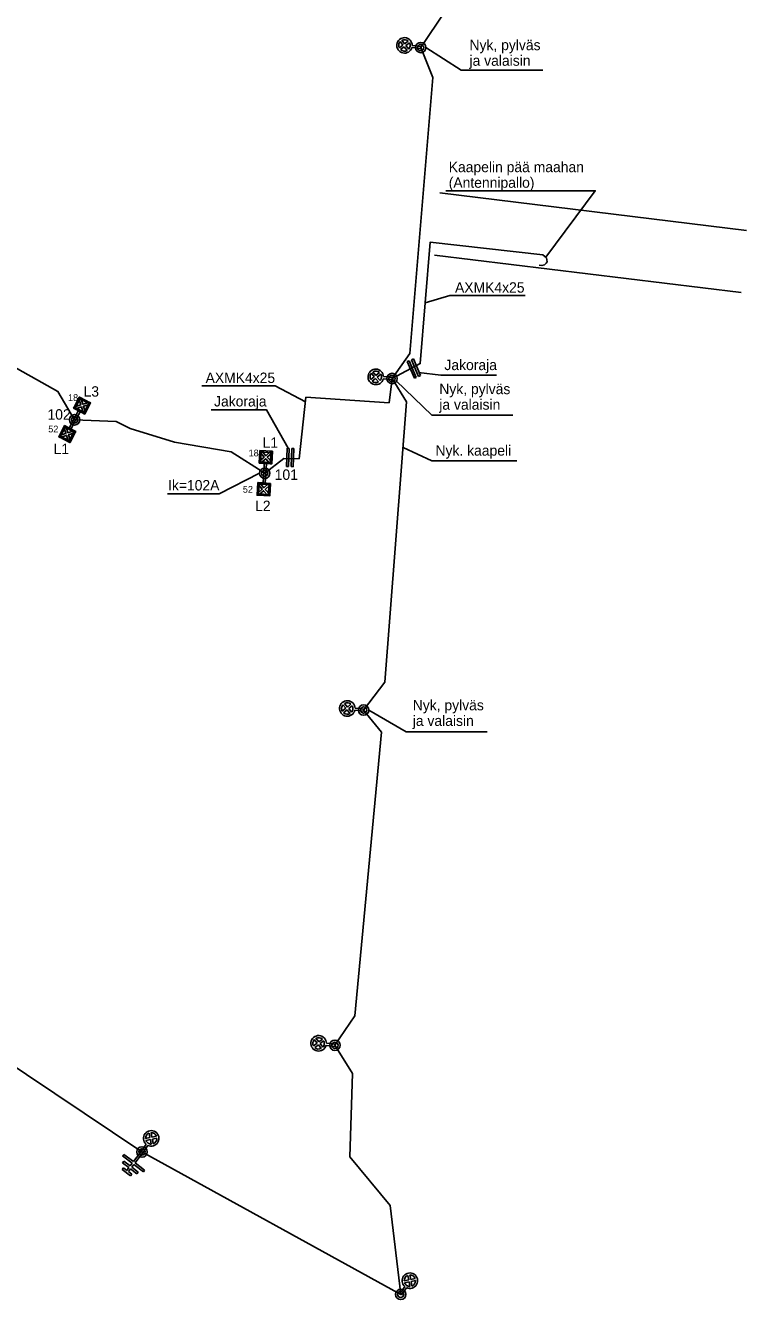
# Model space of a CAD drawing. Extents: x 25497852 to 25498297, y 6686544 to 6687252.
# Drawn here: x 25498193.2 to 25498297.2, y 6686878.8 to 6687062.7 of the extents above; entities that cross this region are included whole.
import ezdxf

# ---------------------------------------------------------------- set-up
doc = ezdxf.new("R2010")
doc.units = 0
for name, color, linetype in [('KayttoOikeusYksikko_piste_tunnus', 7, 'Continuous'), ('KiinteistoNimi', 7, 'Continuous'), ('Rajamerkki_maarekisteripyykki', 7, 'Continuous'), ('Rajamerkki_tonttipyykki', 7, 'Continuous'), ('Rasitealue', 7, 'Continuous'), ('Rasiteviiva', 7, 'Continuous'), ('Taso 1', 7, 'Continuous')]:
    doc.layers.add(name, color=color, linetype=linetype)

msp = doc.modelspace()

# ---------------------------------------------------------------- linework, layer by layer
at = {"layer": 'KayttoOikeusYksikko_piste_tunnus'}
for p, q in [((25498247.66, 6687059.83), (25498247.14, 6687059.43)), ((25498247.26, 6687060.35), (25498247.66, 6687059.83)), ((25498247.32, 6687059.19), (25498247.84, 6687059.59)), ((25498247.9, 6687060.01), (25498247.5, 6687060.54)), ((25498247.84, 6687059.59), (25498248.24, 6687059.06)), ((25498248.43, 6687060.41), (25498247.9, 6687060.01)), ((25498248.08, 6687059.77), (25498248.61, 6687060.17)), ((25498248.48, 6687059.24), (25498248.08, 6687059.77)), ((25498250.2, 6687059.33), (25498248.96, 6687059.5)), ((25498249, 6687059.8), (25498250.24, 6687059.63)), ((25498250.24, 6687059.63), (25498250.2, 6687059.33)), ((25498243.52, 6687011.97), (25498243, 6687011.56)), ((25498243.1, 6687012.49), (25498243.52, 6687011.97)), ((25498243.19, 6687011.32), (25498243.71, 6687011.74)), ((25498243.75, 6687012.16), (25498243.33, 6687012.68)), ((25498243.71, 6687011.74), (25498244.12, 6687011.23)), ((25498244.26, 6687012.58), (25498243.75, 6687012.16)), ((25498243.94, 6687011.93), (25498244.45, 6687012.35)), ((25498244.36, 6687011.42), (25498243.94, 6687011.93)), ((25498246.07, 6687011.57), (25498244.82, 6687011.69)), ((25498244.85, 6687011.99), (25498246.1, 6687011.86)), ((25498246.1, 6687011.86), (25498246.07, 6687011.57)), ((25498239.41, 6686964.11), (25498238.9, 6686963.7)), ((25498238.99, 6686964.63), (25498239.41, 6686964.11)), ((25498239.08, 6686963.46), (25498239.6, 6686963.88)), ((25498239.64, 6686964.3), (25498239.22, 6686964.82)), ((25498239.6, 6686963.88), (25498240.01, 6686963.37)), ((25498240.15, 6686964.72), (25498239.64, 6686964.3)), ((25498239.83, 6686964.07), (25498240.34, 6686964.49)), ((25498240.25, 6686963.56), (25498239.83, 6686964.07)), ((25498241.96, 6686963.7), (25498240.71, 6686963.83)), ((25498240.74, 6686964.13), (25498241.99, 6686964)), ((25498241.99, 6686964), (25498241.96, 6686963.7)), ((25498235.27, 6686915.77), (25498234.75, 6686915.37)), ((25498234.86, 6686916.29), (25498235.27, 6686915.77)), ((25498235.51, 6686915.96), (25498235.1, 6686916.48)), ((25498236.03, 6686916.37), (25498235.51, 6686915.96)), ((25498235.69, 6686915.72), (25498236.21, 6686916.13)), ((25498236.1, 6686915.2), (25498235.69, 6686915.72)), ((25498236.61, 6686915.76), (25498237.85, 6686915.61)), ((25498237.85, 6686915.61), (25498237.82, 6686915.31)), ((25498234.94, 6686915.13), (25498235.46, 6686915.54)), ((25498235.46, 6686915.54), (25498235.86, 6686915.02)), ((25498237.82, 6686915.31), (25498236.57, 6686915.46)), ((25498211.01, 6686902.8), (25498211.14, 6686902.15)), ((25498211.43, 6686902.21), (25498211.31, 6686902.86)), ((25498209.87, 6686900.15), (25498210.57, 6686901.19)), ((25498210.82, 6686901.02), (25498210.12, 6686899.98)), ((25498211.14, 6686902.15), (25498210.49, 6686902.02)), ((25498210.55, 6686901.73), (25498211.2, 6686901.86)), ((25498211.2, 6686901.86), (25498211.32, 6686901.21)), ((25498212.08, 6686902.33), (25498211.43, 6686902.21)), ((25498211.49, 6686901.91), (25498212.14, 6686902.04)), ((25498211.62, 6686901.26), (25498211.49, 6686901.91)), ((25498210.12, 6686899.98), (25498209.87, 6686900.15)), ((25498247.21, 6686879.61), (25498247.91, 6686880.65)), ((25498248.48, 6686881.61), (25498247.83, 6686881.48)), ((25498247.88, 6686881.19), (25498248.53, 6686881.31)), ((25498248.35, 6686882.26), (25498248.48, 6686881.61)), ((25498248.53, 6686881.31), (25498248.66, 6686880.67)), ((25498248.77, 6686881.67), (25498248.64, 6686882.32)), ((25498249.42, 6686881.79), (25498248.77, 6686881.67)), ((25498248.83, 6686881.37), (25498249.48, 6686881.5)), ((25498248.96, 6686880.72), (25498248.83, 6686881.37)), ((25498247.45, 6686879.44), (25498247.21, 6686879.61)), ((25498248.15, 6686880.48), (25498247.45, 6686879.44))]:
    msp.add_line(p, q, dxfattribs=at)
for points in [[(25498200.11, 6687007.42), (25498200.21, 6687007.6), (25498201.77, 6687006.78), (25498201.68, 6687006.61)], [(25498200.93, 6687008.99), (25498200.14, 6687007.48), (25498200.32, 6687007.38), (25498201.11, 6687008.89)], [(25498201.52, 6687006.76), (25498201.25, 6687007.62), (25498200.38, 6687007.35), (25498200.2, 6687007.45), (25498200.29, 6687007.64), (25498201.16, 6687007.91), (25498200.88, 6687008.77), (25498200.98, 6687008.96), (25498201.17, 6687008.86), (25498201.44, 6687008), (25498202.3, 6687008.27), (25498202.49, 6687008.17), (25498202.39, 6687007.98), (25498201.53, 6687007.71), (25498201.8, 6687006.85), (25498201.71, 6687006.66)], [(25498202.43, 6687008.05), (25498202.52, 6687008.22), (25498200.96, 6687009.04), (25498200.86, 6687008.86)], [(25498201.55, 6687006.67), (25498202.4, 6687008.29), (25498202.57, 6687008.2), (25498201.73, 6687006.58)], [(25498200.4, 6687005.68), (25498199.75, 6687004.44), (25498199.49, 6687004.57), (25498200.14, 6687005.82)], [(25498200.14, 6687005.82), (25498200.79, 6687007.07), (25498201.06, 6687006.93), (25498200.4, 6687005.68)], [(25498198.99, 6687004.84), (25498198.15, 6687003.22), (25498197.97, 6687003.31), (25498198.81, 6687004.93)], [(25498199.03, 6687004.75), (25498199.3, 6687003.89), (25498200.16, 6687004.16), (25498200.35, 6687004.06), (25498200.25, 6687003.87), (25498199.39, 6687003.6), (25498199.66, 6687002.74), (25498199.56, 6687002.55), (25498199.37, 6687002.65), (25498199.1, 6687003.51), (25498198.24, 6687003.24), (25498198.05, 6687003.34), (25498198.15, 6687003.53), (25498199.01, 6687003.8), (25498198.74, 6687004.66), (25498198.84, 6687004.85)], [(25498200.43, 6687004.08), (25498200.34, 6687003.91), (25498198.77, 6687004.72), (25498198.87, 6687004.9)], [(25498199.62, 6687002.52), (25498200.4, 6687004.03), (25498200.22, 6687004.12), (25498199.44, 6687002.61)], [(25498198.12, 6687003.46), (25498198.02, 6687003.28), (25498199.59, 6687002.47), (25498199.68, 6687002.64)], [(25498226.99, 6687001.26), (25498226.89, 6686999.56), (25498227.09, 6686999.55), (25498227.19, 6687001.25)], [(25498228.44, 6686999.47), (25498227.84, 6687000.14), (25498227.16, 6686999.55), (25498226.95, 6686999.56), (25498226.96, 6686999.77), (25498227.64, 6687000.37), (25498227.04, 6687001.04), (25498227.05, 6687001.26), (25498227.27, 6687001.24), (25498227.86, 6687000.57), (25498228.54, 6687001.16), (25498228.75, 6687001.15), (25498228.74, 6687000.94), (25498228.06, 6687000.34), (25498228.66, 6686999.67), (25498228.65, 6686999.45)], [(25498228.74, 6687001.01), (25498228.76, 6687001.21), (25498227, 6687001.32), (25498226.98, 6687001.12)], [(25498228.51, 6686999.4), (25498228.62, 6687001.22), (25498228.82, 6687001.21), (25498228.71, 6686999.39)], [(25498226.88, 6686999.5), (25498226.9, 6686999.7), (25498228.66, 6686999.59), (25498228.65, 6686999.39)], [(25498227.56, 6686998.05), (25498227.64, 6686999.45), (25498227.94, 6686999.44), (25498227.86, 6686998.03)], [(25498226.91, 6686996.68), (25498226.8, 6686994.86), (25498226.6, 6686994.87), (25498226.71, 6686996.69)], [(25498226.98, 6686996.61), (25498227.58, 6686995.94), (25498228.25, 6686996.54), (25498228.47, 6686996.52), (25498228.45, 6686996.31), (25498227.78, 6686995.71), (25498228.37, 6686995.04), (25498228.36, 6686994.83), (25498228.15, 6686994.84), (25498227.55, 6686995.51), (25498226.87, 6686994.92), (25498226.66, 6686994.93), (25498226.67, 6686995.14), (25498227.35, 6686995.74), (25498226.75, 6686996.42), (25498226.77, 6686996.63)], [(25498228.53, 6686996.58), (25498228.52, 6686996.38), (25498226.76, 6686996.49), (25498226.77, 6686996.69)], [(25498227.86, 6686998.03), (25498227.77, 6686996.63), (25498227.47, 6686996.65), (25498227.56, 6686998.05)], [(25498228.42, 6686994.82), (25498228.53, 6686996.52), (25498228.33, 6686996.53), (25498228.22, 6686994.83)], [(25498226.67, 6686995.07), (25498226.66, 6686994.87), (25498228.42, 6686994.76), (25498228.43, 6686994.96)]]:
    msp.add_lwpolyline(points, close=True, dxfattribs=at)
for centre, radius, start, end in [((25498247.87, 6687059.8), 1.12, 359.9115, 172.2492), ((25498247.87, 6687059.8), 1.12, 172.2492, 344.587), ((25498247.87, 6687059.8), 0.825, 137.7249, 172.2492), ((25498247.87, 6687059.8), 0.825, 172.2492, 206.7736), ((25498247.87, 6687059.8), 0.825, 227.7249, 296.7736), ((25498247.87, 6687059.8), 0.825, 47.7249, 116.7736), ((25498247.87, 6687059.8), 0.825, 317.7249, 352.2492), ((25498247.87, 6687059.8), 0.825, 352.2492, 26.7736), ((25498243.73, 6687011.95), 1.12, 1.8898, 174.2275), ((25498243.73, 6687011.95), 1.12, 174.2275, 346.5652), ((25498243.73, 6687011.95), 0.825, 174.2275, 208.7518), ((25498243.73, 6687011.95), 0.825, 139.7032, 174.2275), ((25498243.73, 6687011.95), 0.825, 229.7032, 298.7518), ((25498243.73, 6687011.95), 0.825, 49.7032, 118.7518), ((25498243.73, 6687011.95), 0.825, 319.7032, 354.2275), ((25498243.73, 6687011.95), 0.825, 354.2275, 28.7518), ((25498239.62, 6686964.09), 1.12, 174.1431, 346.4809), ((25498239.62, 6686964.09), 1.12, 1.8054, 174.1431), ((25498239.62, 6686964.09), 0.825, 174.1431, 208.6674), ((25498239.62, 6686964.09), 0.825, 139.6188, 174.1431), ((25498239.62, 6686964.09), 0.825, 229.6188, 298.6674), ((25498239.62, 6686964.09), 0.825, 49.6188, 118.6674), ((25498239.62, 6686964.09), 0.825, 319.6188, 354.1431), ((25498239.62, 6686964.09), 0.825, 354.1431, 28.6674), ((25498235.48, 6686915.75), 1.12, 173.0866, 345.4243), ((25498235.48, 6686915.75), 1.12, 0.7488, 173.0866), ((25498235.48, 6686915.75), 0.825, 138.5623, 173.0866), ((25498235.48, 6686915.75), 0.825, 173.0866, 207.6109), ((25498235.48, 6686915.75), 0.825, 48.5623, 117.6109), ((25498235.48, 6686915.75), 0.825, 318.5623, 353.0866), ((25498235.48, 6686915.75), 0.825, 353.0866, 27.6109), ((25498235.48, 6686915.75), 0.825, 228.5623, 297.6109), ((25498211.32, 6686902.03), 1.12, 56.0415, 228.3793), ((25498211.32, 6686902.03), 0.825, 111.5172, 180.5658), ((25498211.32, 6686902.03), 1.12, 243.7038, 56.0415), ((25498211.32, 6686902.03), 0.825, 56.0415, 90.5658), ((25498211.32, 6686902.03), 0.825, 21.5172, 56.0415), ((25498211.32, 6686902.03), 0.825, 201.5172, 236.0415), ((25498211.32, 6686902.03), 0.825, 236.0415, 270.5658), ((25498211.32, 6686902.03), 0.825, 291.5172, 0.5658), ((25498248.65, 6686881.49), 1.12, 56.1117, 228.4495), ((25498248.65, 6686881.49), 0.825, 111.5874, 180.6361), ((25498248.65, 6686881.49), 0.825, 201.5874, 236.1117), ((25498248.65, 6686881.49), 1.12, 243.774, 56.1117), ((25498248.65, 6686881.49), 0.825, 236.1117, 270.6361), ((25498248.65, 6686881.49), 0.825, 56.1117, 90.6361), ((25498248.65, 6686881.49), 0.825, 291.5874, 0.6361), ((25498248.65, 6686881.49), 0.825, 21.5874, 56.1117)]:
    msp.add_arc(centre, radius, start, end, dxfattribs=at)
at = {"layer": 'KiinteistoNimi'}
for centre, radius in [((25498250.22, 6687059.49), 0.75), ((25498250.22, 6687059.49), 0.45), ((25498246.09, 6687011.72), 0.75), ((25498246.09, 6687011.72), 0.45), ((25498200.27, 6687005.75), 0.75), ((25498200.27, 6687005.75), 0.75), ((25498200.27, 6687005.75), 0.45), ((25498200.27, 6687005.75), 0.45), ((25498227.71, 6686998.04), 0.75), ((25498227.71, 6686998.04), 0.45), ((25498241.98, 6686963.86), 0.75), ((25498241.98, 6686963.86), 0.45), ((25498237.84, 6686915.47), 0.75), ((25498237.84, 6686915.47), 0.45), ((25498209.99, 6686900.07), 0.75), ((25498209.99, 6686900.07), 0.45), ((25498247.33, 6686879.52), 0.75), ((25498247.33, 6686879.52), 0.45)]:
    msp.add_circle(centre, radius, dxfattribs=at)
at = {"layer": 'Rajamerkki_maarekisteripyykki'}
for p, q in [((25498252.97, 6687038.5), (25498297.24, 6687033.1)), ((25498252.2, 6687029.53), (25498296.47, 6687024.12))]:
    msp.add_line(p, q, dxfattribs=at)
at = {"layer": 'Rajamerkki_tonttipyykki'}
for p, q in [((25498248.27, 6687014.17), (25498248.55, 6687014.28)), ((25498249.3, 6687011.75), (25498248.27, 6687014.17)), ((25498248.55, 6687014.28), (25498249.57, 6687011.87)), ((25498248.9, 6687014.43), (25498249.17, 6687014.55)), ((25498249.92, 6687012.02), (25498248.9, 6687014.43)), ((25498249.17, 6687014.55), (25498250.2, 6687012.13)), ((25498249.57, 6687011.87), (25498249.3, 6687011.75)), ((25498250.2, 6687012.13), (25498249.92, 6687012.02)), ((25498230.85, 6686999.02), (25498230.94, 6687001.64)), ((25498230.94, 6687001.64), (25498231.24, 6687001.63)), ((25498231.24, 6687001.63), (25498231.15, 6686999.01)), ((25498231.53, 6686999), (25498231.62, 6687001.62)), ((25498231.62, 6687001.62), (25498231.92, 6687001.61)), ((25498231.92, 6687001.61), (25498231.83, 6686998.98)), ((25498231.15, 6686999.01), (25498230.85, 6686999.02)), ((25498231.83, 6686998.98), (25498231.53, 6686999)), ((25498207.2, 6686899.49), (25498207.38, 6686899.72)), ((25498208.57, 6686898.44), (25498207.2, 6686899.49)), ((25498207.38, 6686899.72), (25498208.75, 6686898.68)), ((25498208.75, 6686898.68), (25498209.87, 6686900.16)), ((25498210.11, 6686899.98), (25498208.99, 6686898.5)), ((25498209.87, 6686900.16), (25498210.11, 6686899.98)), ((25498207.13, 6686897.53), (25498207.31, 6686897.77)), ((25498208.32, 6686896.62), (25498207.13, 6686897.53)), ((25498207.16, 6686898.51), (25498207.35, 6686898.75)), ((25498208.09, 6686897.81), (25498207.16, 6686898.51)), ((25498207.31, 6686897.77), (25498207.79, 6686897.41)), ((25498207.35, 6686898.75), (25498208.27, 6686898.05)), ((25498207.79, 6686897.41), (25498208.09, 6686897.81)), ((25498208.33, 6686897.62), (25498208.03, 6686897.23)), ((25498208.03, 6686897.23), (25498208.51, 6686896.86)), ((25498208.27, 6686898.05), (25498208.57, 6686898.44)), ((25498209.26, 6686896.92), (25498208.33, 6686897.62)), ((25498208.81, 6686898.26), (25498208.51, 6686897.86)), ((25498208.51, 6686897.86), (25498209.44, 6686897.16)), ((25498210.19, 6686897.22), (25498208.81, 6686898.26)), ((25498208.99, 6686898.5), (25498210.37, 6686897.46)), ((25498210.37, 6686897.46), (25498210.19, 6686897.22)), ((25498208.51, 6686896.86), (25498208.32, 6686896.62)), ((25498209.44, 6686897.16), (25498209.26, 6686896.92))]:
    msp.add_line(p, q, dxfattribs=at)
at = {"layer": 'Rasitealue'}
for p, q in [((25498177.4, 6686921.82), (25498209.99, 6686900.07)), ((25498209.99, 6686900.07), (25498247.33, 6686879.52))]:
    msp.add_line(p, q, dxfattribs=at)
for points in [[(25498254.07, 6687104.33), (25498257, 6687100.45), (25498253.77, 6687064.73), (25498250.22, 6687059.49)], [(25498250.22, 6687059.49), (25498251.96, 6687055.15), (25498248.64, 6687015.33), (25498246.09, 6687011.72)], [(25498246.09, 6687011.72), (25498250.14, 6687013.87), (25498251.6, 6687031.42), (25498267.85, 6687029.58), (25498268.35, 6687029.13), (25498268.49, 6687028.57), (25498268.31, 6687028.35), (25498268.09, 6687028.13), (25498267.72, 6687028.01), (25498267.31, 6687028.08)], [(25498200.27, 6687005.75), (25498197.85, 6687009.86), (25498181.51, 6687018.98), (25498176.94, 6687018.9)], [(25498227.71, 6686998.04), (25498230.44, 6687000.15), (25498232.67, 6687000.14), (25498233.66, 6687009.02), (25498245.66, 6687008.21), (25498246.09, 6687011.72)], [(25498246.09, 6687011.72), (25498248.18, 6687008.34), (25498245.03, 6686967.87), (25498241.98, 6686963.86)], [(25498227.71, 6686998.04), (25498222.86, 6687001.14), (25498214.69, 6687002.55), (25498208.26, 6687004.51), (25498206.28, 6687005.51), (25498200.27, 6687005.75)], [(25498241.98, 6686963.86), (25498244.55, 6686960.66), (25498240.72, 6686919.7), (25498237.84, 6686915.47)], [(25498237.84, 6686915.47), (25498240.38, 6686911.4), (25498239.99, 6686899.35), (25498245.81, 6686892.35), (25498247.33, 6686879.52)]]:
    msp.add_lwpolyline(points, dxfattribs=at)
at = {"layer": 'Taso 1'}
for points in [[(25498267.86, 6687056.22), (25498256.06, 6687056.22), (25498250.97, 6687059.49)], [(25498253.82, 6687038.82), (25498275.42, 6687038.82), (25498268.26, 6687029.22)], [(25498265.3, 6687023.72), (25498254.43, 6687023.72), (25498250.87, 6687022.64)], [(25498263.51, 6687006.43), (25498251.83, 6687006.43), (25498246.69, 6687011.39)], [(25498261.18, 6687012.19), (25498253.1, 6687012.19), (25498249.89, 6687012.58)], [(25498218.65, 6687010.68), (25498229.19, 6687010.68), (25498233.59, 6687008.37)], [(25498219.96, 6687007.19), (25498227.97, 6687007.19), (25498231.09, 6687001.64)], [(25498264.07, 6686999.84), (25498251.82, 6686999.84), (25498247.7, 6687001.76)], [(25498213.69, 6686995.06), (25498221.11, 6686995.06), (25498226.96, 6686998.04)], [(25498259.81, 6686960.72), (25498248.13, 6686960.72), (25498242.73, 6686963.86)]]:
    msp.add_lwpolyline(points, dxfattribs=at)

# ---------------------------------------------------------------- texts
at = {"layer": 'Rasiteviiva'}
for s, height, p in [('Nyk, pylväs', 1.5, (25498257.26, 6687059.11)), ('ja valaisin', 1.5, (25498257.26, 6687056.86)), ('Kaapelin pää maahan', 1.5, (25498254.26, 6687041.5)), ('(Antennipallo)', 1.5, (25498254.26, 6687039.25)), ('AXMK4x25', 1.5, (25498255.17, 6687024.11)), ('Jakoraja', 1.5, (25498253.64, 6687012.93)), ('AXMK4x25', 1.5, (25498219.17, 6687011.07)), ('18', 0.975, (25498199.32, 6687008.48)), ('L3', 1.5, (25498201.56, 6687009.1)), ('Nyk, pylväs', 1.5, (25498252.9, 6687009.46)), ('Jakoraja', 1.5, (25498220.39, 6687007.68)), ('ja valaisin', 1.5, (25498252.9, 6687007.21)), ('102', 1.5, (25498196.35, 6687005.78)), ('52', 0.975, (25498196.46, 6687003.94)), ('L1', 1.5, (25498197.24, 6687000.81)), ('L1', 1.5, (25498227.41, 6687001.72)), ('Nyk. kaapeli', 1.5, (25498252.35, 6687000.58)), ('18', 0.975, (25498225.38, 6687000.48)), ('101', 1.5, (25498229.14, 6686997.09)), ('Ik=102A', 1.5, (25498213.75, 6686995.56)), ('52', 0.975, (25498224.55, 6686995.23)), ('L2', 1.5, (25498226.32, 6686992.59)), ('Nyk, pylväs', 1.5, (25498249.07, 6686963.82)), ('ja valaisin', 1.5, (25498249.07, 6686961.57))]:
    msp.add_text(s, height=height, dxfattribs=at).set_placement(p)

doc.saveas('drawing.dxf')
